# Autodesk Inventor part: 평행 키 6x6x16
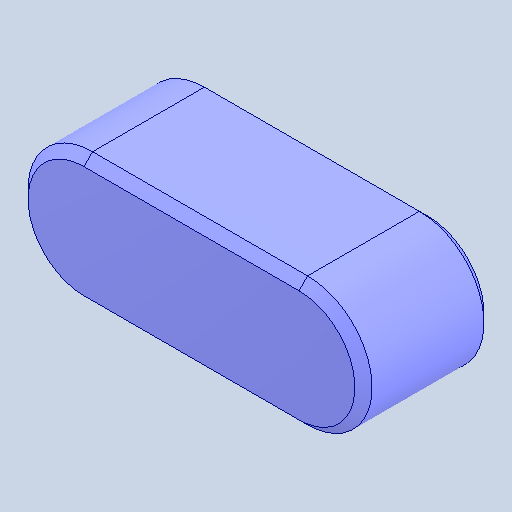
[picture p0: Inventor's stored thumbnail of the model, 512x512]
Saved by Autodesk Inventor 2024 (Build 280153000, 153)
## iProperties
Created: 2025-11
Part Number: 평행 키 6x6x16
Material: 강철, 연강
Description: 키 및 해당 키홈
Document SubType Name: Modeling
Designer: Edu07
Density: 7.85 g/cm^3
Appearance: 기본값
Author: jhkim
Sending System: Autodesk Inventor 2026
Preprocessor: ST-DEVELOPER v20.1
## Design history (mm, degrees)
node "평행 키 6x6x161"
node "솔리드1"
body "Solid1"
